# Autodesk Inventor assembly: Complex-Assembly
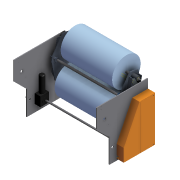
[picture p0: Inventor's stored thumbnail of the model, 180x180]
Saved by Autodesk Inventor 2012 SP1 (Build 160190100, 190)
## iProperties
Shininess: 0.0
Created: 2000-12
Part Number: Complex-Assembly
Checked By: PT
Document SubType Name: Assembly
Designer: Gary
Density: 0.0
Volumn: 0.0
Area: 0.0
PropertySet Name: Model Information
Control State: 0
Master: False
Checked Out: False
sheet: 200A
Title: Large Assembly Management
Author: Administrator
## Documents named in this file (19)
- D:\AOTC\Autodesk Inventor 2012 Essential for New Users\Autodesk Inventor 2011 Esentials - Project Files\Learning\Workspace\Complex-Assembly.iam
- D:\AOTC\Autodesk Inventor 2012 Essential for New Users\Autodesk Inventor 2011 Esentials - Project Files\Learning\Workspace\Parts\ADSK-103945.ipt
- D:\AOTC\Autodesk Inventor 2012 Essential for New Users\Autodesk Inventor 2011 Esentials - Project Files\Learning\Workspace\Sub-Assemblies\ADSK-103183.iam
- D:\AOTC\Autodesk Inventor 2012 Essential for New Users\Autodesk Inventor 2011 Esentials - Project Files\Learning\Workspace\Sub-Assemblies\ADSK-103248.iam
- D:\AOTC\Autodesk Inventor 2012 Essential for New Users\Autodesk Inventor 2011 Esentials - Project Files\Learning\Workspace\Sub-Assemblies\ADSK-103246.iam
- D:\AOTC\Autodesk Inventor 2012 Essential for New Users\Autodesk Inventor 2011 Esentials - Project Files\Learning\Workspace\Parts\ADSK-103990.ipt
- D:\AOTC\Autodesk Inventor 2012 Essential for New Users\Autodesk Inventor 2011 Esentials - Project Files\Learning\Workspace\Parts\ADSK-103404.ipt
- D:\AOTC\Autodesk Inventor 2012 Essential for New Users\Autodesk Inventor 2011 Esentials - Project Files\Learning\Workspace\Parts\ADSK-103629.ipt
- D:\AOTC\Autodesk Inventor 2012 Essential for New Users\Autodesk Inventor 2011 Esentials - Project Files\Learning\Workspace\Parts\ADSK-103462.ipt
- D:\AOTC\Autodesk Inventor 2012 Essential for New Users\Autodesk Inventor 2011 Esentials - Project Files\Learning\Workspace\Parts\ADSK-103513.ipt
- D:\AOTC\Autodesk Inventor 2012 Essential for New Users\Autodesk Inventor 2011 Esentials - Project Files\Learning\Workspace\Sub-Assemblies\ADSK-103046.iam
- D:\AOTC\Autodesk Inventor 2012 Essential for New Users\Autodesk Inventor 2011 Esentials - Project Files\Learning\Workspace\Parts\ADSK-104017.ipt
- D:\AOTC\Autodesk Inventor 2012 Essential for New Users\Autodesk Inventor 2011 Esentials - Project Files\Learning\Workspace\Sub-Assemblies\ADSK-103069.iam
- D:\AOTC\Autodesk Inventor 2012 Essential for New Users\Autodesk Inventor 2011 Esentials - Project Files\Learning\Workspace\Parts\ADSK-104046.ipt
- D:\AOTC\Autodesk Inventor 2012 Essential for New Users\Autodesk Inventor 2011 Esentials - Project Files\Learning\Workspace\Sub-Assemblies\ADSK-103239.iam
- D:\AOTC\Autodesk Inventor 2012 Essential for New Users\Autodesk Inventor 2011 Esentials - Project Files\Learning\Workspace\Parts\ADSK-103914.ipt
- D:\AOTC\Autodesk Inventor 2012 Essential for New Users\Autodesk Inventor 2011 Esentials - Project Files\Learning\Workspace\Parts\ADSK-103512.ipt
- D:\AOTC\Autodesk Inventor 2012 Essential for New Users\Autodesk Inventor 2011 Esentials - Project Files\Learning\Workspace\Sub-Assemblies\ADSK-103057.iam
- D:\AOTC\Autodesk Inventor 2012 Essential for New Users\Autodesk Inventor 2011 Esentials - Project Files\Learning\Workspace\Sub-Assemblies\Design Accelerator\Bolted Connection2.iam
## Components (32 placed, 18 different names)
1. ADSK-103945:1 — Flush:1, Flush:2, Insert:1, Mate:3, Angle:2, Insert:5, Angle:3, Angle:6, Mate:12, Mate:23, Mate:25, Mate:27
2. ADSK-103945:2 — Flush:1, Flush:2, Insert:2, Mate:2, Insert:6, Angle:4, Insert:7, Angle:5, Flush:6, Flush:7, Flush:8, Mate:15, Mate:17, Mate:18, Mate:20
3. ADSK-103183:1 [sub-assembly] — Insert:1, Insert:4
4. ADSK-103183:2 [sub-assembly] — Insert:2, Insert:3
5. ADSK-103248:1 [sub-assembly] — Insert:3, Angle:1, Mate:1, Mate:4, Mate:5, Mate:6, Mate:7, Mate:10, Flush:5, Mate:31, Mate:32, Mate:33, Angle:8
6. ADSK-103246:1 [sub-assembly] — Insert:4, Angle:1, Mate:1, Angle:2, Mate:8, Flush:3, Insert:11, Insert:12, Insert:14, Mate:13, Mate:30
7. ADSK-103239:1 [sub-assembly] — Mate:2, Mate:9, Insert:10, Mate:11
8. ADSK-104046:1 — Mate:3, Insert:13
9. ADSK-103914:1 — Mate:4, Mate:5
10. ADSK-103914:2 — Mate:6, Mate:7
11. ADSK-103057:1 [sub-assembly] — Insert:5, Angle:3, Mate:22, Mate:24, Mate:26
12. ADSK-103057:2 [sub-assembly] — Insert:7, Angle:5, Mate:14, Mate:16, Mate:19, Mate:21
13. ADSK-103057:3 [sub-assembly] — Insert:6, Angle:4
14. ADSK-103512:1 — Mate:8, Mate:9, Flush:3, Flush:4, Insert:8
15. ADSK-103512:2 — Mate:10, Flush:4, Flush:5, Insert:9
16. ADSK-103990:1 — Insert:8, Insert:10
17. ADSK-103990:2 — Insert:9
18. ADSK-103404:1 — Insert:11
19. ADSK-103404:2 — Insert:12
20. ADSK-103629:1 — Insert:13, Angle:6, Mate:11
21. ADSK-103462:1 — Insert:14
22. ADSK-103513:1 — Mate:12, Mate:13, Angle:7
23. ADSK-103046:1 [sub-assembly] — Angle:7, Mate:28, Mate:29, Mate:30
24. ADSK-104017:1 — Mate:28, Mate:29
25. ADSK-103069:1 [sub-assembly] — Flush:6, Flush:7, Flush:8
26. Bolted Connection:1 [sub-assembly] — Mate:14, Mate:15
27. Bolted Connection:2 [sub-assembly] — Mate:16, Mate:17
28. Bolted Connection:3 [sub-assembly] — Mate:18, Mate:19
29. Bolted Connection:4 [sub-assembly] — Mate:20, Mate:21
30. Bolted Connection:5 [sub-assembly] — Mate:22, Mate:23
31. Bolted Connection:6 [sub-assembly] — Mate:24, Mate:25
32. Bolted Connection:7 [sub-assembly] — Mate:26, Mate:27
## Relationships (63: Mate 33, Insert 14, Flush 8, Angle 8)
- Flush:1: ADSK-103945:1 ↔ ADSK-103945:2
- Flush:2: ADSK-103945:1 ↔ ADSK-103945:2
- Insert:1: ADSK-103945:1 ↔ ADSK-103183:1
- Insert:2: ADSK-103945:2 ↔ ADSK-103183:2
- Insert:3: ADSK-103183:2 ↔ ADSK-103248:1
- Insert:4: ADSK-103183:1 ↔ ADSK-103246:1
- Angle:1: ADSK-103248:1 ↔ ADSK-103246:1
- Mate:1: ADSK-103248:1 ↔ ADSK-103246:1
- Mate:2: ADSK-103945:2 ↔ ADSK-103239:1
- Mate:3: ADSK-103945:1 ↔ ADSK-104046:1
- Angle:2: ADSK-103945:1 ↔ ADSK-103246:1
- Mate:4: ADSK-103248:1 ↔ ADSK-103914:1
- Mate:5: ADSK-103248:1 ↔ ADSK-103914:1
- Mate:6: ADSK-103248:1 ↔ ADSK-103914:2
- Mate:7: ADSK-103248:1 ↔ ADSK-103914:2
- Insert:5: ADSK-103945:1 ↔ ADSK-103057:1
- Angle:3: ADSK-103945:1 ↔ ADSK-103057:1
- Insert:6: ADSK-103945:2 ↔ ADSK-103057:3
- Angle:4: ADSK-103945:2 ↔ ADSK-103057:3
- Insert:7: ADSK-103945:2 ↔ ADSK-103057:2
- Angle:5: ADSK-103945:2 ↔ ADSK-103057:2
- Mate:8: ADSK-103246:1 ↔ ADSK-103512:1
- Mate:9: ADSK-103239:1 ↔ ADSK-103512:1
- Flush:3: ADSK-103246:1 ↔ ADSK-103512:1
- Mate:10: ADSK-103248:1 ↔ ADSK-103512:2
- Flush:4: ADSK-103512:1 ↔ ADSK-103512:2
- Flush:5: ADSK-103248:1 ↔ ADSK-103512:2
- Insert:8: ADSK-103512:1 ↔ ADSK-103990:1
- Insert:9: ADSK-103512:2 ↔ ADSK-103990:2
- Insert:10: ADSK-103239:1 ↔ ADSK-103990:1
- Insert:11: ADSK-103246:1 ↔ ADSK-103404:1
- Insert:12: ADSK-103246:1 ↔ ADSK-103404:2
- Insert:13: ADSK-104046:1 ↔ ADSK-103629:1
- Angle:6: ADSK-103945:1 ↔ ADSK-103629:1
- Mate:11: ADSK-103239:1 ↔ ADSK-103629:1
- Insert:14: ADSK-103246:1 ↔ ADSK-103462:1
- Mate:12: ADSK-103945:1 ↔ ADSK-103513:1
- Mate:13: ADSK-103246:1 ↔ ADSK-103513:1
- Flush:6: ADSK-103945:2 ↔ ADSK-103069:1
- Flush:7: ADSK-103945:2 ↔ ADSK-103069:1
- Flush:8: ADSK-103945:2 ↔ ADSK-103069:1
- Angle:7: ADSK-103513:1 ↔ ADSK-103046:1
- Mate:14: ADSK-103057:2 ↔ Bolted Connection:1
- Mate:15: ADSK-103945:2 ↔ Bolted Connection:1
- Mate:16: ADSK-103057:2 ↔ Bolted Connection:2
- Mate:17: ADSK-103945:2 ↔ Bolted Connection:2
- Mate:18: ADSK-103945:2 ↔ Bolted Connection:3
- Mate:19: ADSK-103057:2 ↔ Bolted Connection:3
- Mate:20: ADSK-103945:2 ↔ Bolted Connection:4
- Mate:21: ADSK-103057:2 ↔ Bolted Connection:4
- Mate:22: ADSK-103057:1 ↔ Bolted Connection:5
- Mate:23: ADSK-103945:1 ↔ Bolted Connection:5
- Mate:24: ADSK-103057:1 ↔ Bolted Connection:6
- Mate:25: ADSK-103945:1 ↔ Bolted Connection:6
- Mate:26: ADSK-103057:1 ↔ Bolted Connection:7
- Mate:27: ADSK-103945:1 ↔ Bolted Connection:7
- Mate:28: ADSK-103046:1 ↔ ADSK-104017:1
- Mate:29: ADSK-103046:1 ↔ ADSK-104017:1
- Mate:30: ADSK-103246:1 ↔ ADSK-103046:1
- Mate:31: ADSK-103248:1
- Mate:32: ADSK-103248:1
- Mate:33: ADSK-103248:1
- Angle:8: ADSK-103248:1
